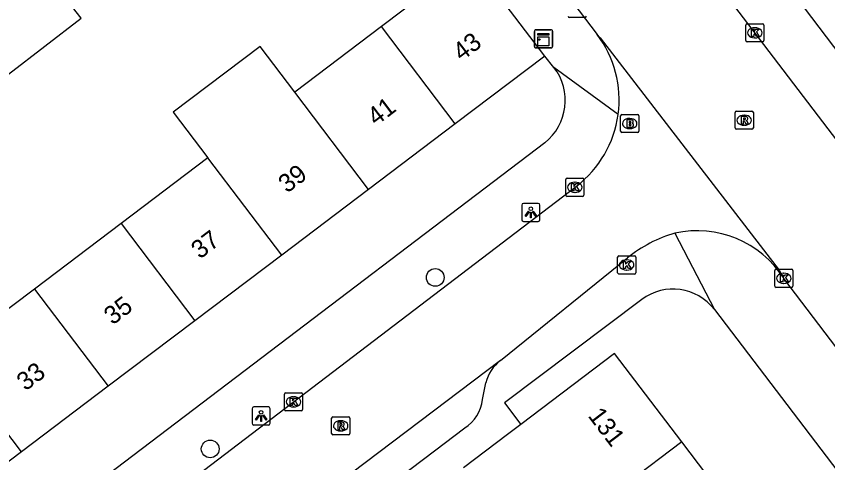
# Model space of a CAD drawing. Extents: x 160037 to 160839, y 385326 to 386441.
# Drawn here: x 160326.7 to 160371.43, y 385868.72 to 385893.36 of the extents above; entities that cross this region are included whole.
import ezdxf

# ---------------------------------------------------------------- set-up
doc = ezdxf.new("R2010")
doc.units = 0
for name, color, linetype in [('IMGEO_Boom', 7, 'Continuous'), ('IMGEO_Brandkraan', 7, 'Continuous'), ('IMGEO_Kast', 7, 'Continuous'), ('IMGEO_Kolk', 7, 'Continuous'), ('IMGEO_Lichtpunt', 7, 'Continuous'), ('IMGEO_Pand', 7, 'Continuous'), ('IMGEO_Pand_nummerreeks', 7, 'Continuous'), ('IMGEO_Rijbaan_lokaal_open', 7, 'Continuous'), ('IMGEO_Rioolput', 7, 'Continuous'), ('IMGEO_Voetpad_open', 7, 'Continuous')]:
    doc.layers.add(name, color=color, linetype=linetype)

msp = doc.modelspace()

# ---------------------------------------------------------------- linework, layer by layer
at = {"layer": 'IMGEO_Boom'}
for centre in [(160349.794, 385878.947), (160337.388, 385869.482)]:
    msp.add_circle(centre, 0.489, dxfattribs=at)
at = {"layer": 'IMGEO_Brandkraan'}
for p, q in [((160360.014, 385887.015), (160360.014, 385887.867)), ((160360.089, 385887.941), (160360.941, 385887.941)), ((160361.015, 385887.867), (160361.015, 385887.015)), ((160360.502, 385887.721), (160360.527, 385887.721)), ((160360.941, 385886.941), (160360.089, 385886.941)), ((160360.525, 385887.161), (160360.5, 385887.161))]:
    msp.add_line(p, q, dxfattribs=at)
for points in [[(160360.014, 385887.015), (160360.014, 385887.867)], [(160360.089, 385887.941), (160360.941, 385887.941)], [(160361.015, 385887.867), (160361.015, 385887.015)], [(160360.362, 385887.641), (160360.362, 385887.241), (160360.575, 385887.241)], [(160360.593, 385887.641), (160360.362, 385887.641)], [(160360.541, 385887.56), (160360.487, 385887.56), (160360.487, 385887.484)], [(160360.487, 385887.484), (160360.54, 385887.484)], [(160360.549, 385887.408), (160360.487, 385887.408), (160360.487, 385887.327)], [(160360.487, 385887.327), (160360.549, 385887.327)], [(160360.941, 385886.941), (160360.089, 385886.941)]]:
    msp.add_lwpolyline(points, dxfattribs=at)
for centre, radius, start, end in [((160360.091, 385887.865), 0.0765, 91.552, 178.448), ((160360.091, 385887.865), 0.0765, 91.552, 178.448), ((160360.939, 385887.865), 0.0765, 1.552, 88.448), ((160360.939, 385887.865), 0.0765, 1.552, 88.448), ((160360.542, 385887.522), 0.0379, 267.8285, 90.9355), ((160360.55, 385887.367), 0.0404, 269.8759, 90.5077), ((160360.597, 385887.496), 0.145, 59.4692, 91.5367), ((160360.622, 385887.543), 0.0922, 285.5137, 58.1501), ((160360.627, 385887.351), 0.105, 301.3115, 78.989), ((160360.091, 385887.017), 0.0765, 181.552, 268.448), ((160360.091, 385887.017), 0.0765, 181.552, 268.448), ((160360.581, 385887.492), 0.251, 268.6676, 293.5347), ((160360.939, 385887.017), 0.0765, 271.552, 358.448), ((160360.939, 385887.017), 0.0765, 271.552, 358.448)]:
    msp.add_arc(centre, radius, start, end, dxfattribs=at)
for centre, major_axis, ratio, start_param, end_param in [((160360.501, 385887.441), (-0.387, 0.002), 0.722429, 4.712389, 7.853982), ((160360.526, 385887.441), (-0.39, 0.002), 0.717154, 1.570796, 4.712389)]:
    msp.add_ellipse(centre, major_axis=major_axis, ratio=ratio, start_param=start_param, end_param=end_param, dxfattribs=at)
at = {"layer": 'IMGEO_Kast'}
for p, q in [((160355.259, 385891.688), (160355.259, 385892.529)), ((160355.259, 385892.529), (160355.259, 385891.688)), ((160355.334, 385892.613), (160356.175, 385892.613)), ((160356.175, 385892.613), (160355.334, 385892.613)), ((160356.259, 385892.538), (160356.259, 385891.697)), ((160356.259, 385891.697), (160356.259, 385892.538)), ((160356.184, 385891.613), (160355.343, 385891.613)), ((160355.343, 385891.613), (160356.184, 385891.613))]:
    msp.add_line(p, q, dxfattribs=at)
for points in [[(160355.454, 385892.403), (160356.054, 385892.403), (160356.054, 385892.318), (160355.454, 385892.318), (160355.454, 385892.403)], [(160355.454, 385892.228), (160356.054, 385892.228), (160356.054, 385891.739), (160355.454, 385891.739), (160355.454, 385892.228)]]:
    msp.add_lwpolyline(points, dxfattribs=at)
msp.add_circle((160355.538, 385892.077), 0.0377, dxfattribs=at)
for centre, start, end in [((160355.337, 385892.535), 92.4484, 184.2845), ((160355.337, 385892.535), 92.4484, 184.2845), ((160356.181, 385892.535), 2.4484, 94.2845), ((160356.181, 385892.535), 2.4484, 94.2845), ((160355.337, 385891.691), 182.4484, 274.2845), ((160355.337, 385891.691), 182.4484, 274.2845), ((160356.181, 385891.691), 272.4484, 4.2845), ((160356.181, 385891.691), 272.4484, 4.2845)]:
    msp.add_arc(centre, 0.0779, start, end, dxfattribs=at)
at = {"layer": 'IMGEO_Kolk'}
for p, q in [((160358.053, 385893.291), (160357.201, 385893.291)), ((160366.908, 385892.025), (160366.908, 385892.877)), ((160366.983, 385892.951), (160367.835, 385892.951)), ((160367.396, 385892.731), (160367.421, 385892.731)), ((160367.909, 385892.877), (160367.909, 385892.025)), ((160367.835, 385891.951), (160366.983, 385891.951)), ((160367.419, 385892.171), (160367.394, 385892.171)), ((160356.989, 385883.498), (160356.989, 385884.35)), ((160357.064, 385884.424), (160357.916, 385884.424)), ((160357.477, 385884.204), (160357.502, 385884.204)), ((160357.99, 385884.35), (160357.99, 385883.498)), ((160357.916, 385883.424), (160357.064, 385883.424)), ((160357.5, 385883.644), (160357.475, 385883.644)), ((160359.922, 385880.137), (160360.774, 385880.137)), ((160359.847, 385879.211), (160359.847, 385880.063)), ((160360.335, 385879.917), (160360.36, 385879.917)), ((160360.848, 385880.063), (160360.848, 385879.211)), ((160360.358, 385879.357), (160360.333, 385879.357)), ((160368.507, 385878.475), (160368.507, 385879.327)), ((160368.582, 385879.401), (160369.434, 385879.401)), ((160369.508, 385879.327), (160369.508, 385878.475)), ((160360.774, 385879.137), (160359.922, 385879.137)), ((160368.995, 385879.181), (160369.02, 385879.181)), ((160369.434, 385878.401), (160368.582, 385878.401)), ((160369.018, 385878.621), (160368.993, 385878.621)), ((160341.555, 385872.584), (160342.407, 385872.584)), ((160341.48, 385871.658), (160341.48, 385872.51)), ((160341.968, 385872.364), (160341.993, 385872.364)), ((160342.481, 385872.51), (160342.481, 385871.658)), ((160341.991, 385871.804), (160341.966, 385871.804)), ((160342.407, 385871.584), (160341.555, 385871.584))]:
    msp.add_line(p, q, dxfattribs=at)
for points in [[(160358.053, 385893.291), (160357.201, 385893.291)], [(160366.908, 385892.025), (160366.908, 385892.877)], [(160366.983, 385892.951), (160367.835, 385892.951)], [(160367.909, 385892.877), (160367.909, 385892.025)], [(160367.229, 385892.651), (160367.352, 385892.651), (160367.352, 385892.5), (160367.482, 385892.651), (160367.646, 385892.651), (160367.5, 385892.5), (160367.653, 385892.251), (160367.501, 385892.251), (160367.416, 385892.415), (160367.352, 385892.348), (160367.352, 385892.251), (160367.229, 385892.251), (160367.229, 385892.651)], [(160367.835, 385891.951), (160366.983, 385891.951)], [(160356.989, 385883.498), (160356.989, 385884.35)], [(160357.064, 385884.424), (160357.916, 385884.424)], [(160357.99, 385884.35), (160357.99, 385883.498)], [(160357.31, 385884.124), (160357.433, 385884.124), (160357.433, 385883.973), (160357.563, 385884.124), (160357.727, 385884.124), (160357.581, 385883.973), (160357.734, 385883.724), (160357.582, 385883.724), (160357.497, 385883.888), (160357.433, 385883.821), (160357.433, 385883.724), (160357.31, 385883.724), (160357.31, 385884.124)], [(160357.916, 385883.424), (160357.064, 385883.424)], [(160359.922, 385880.137), (160360.774, 385880.137)], [(160359.847, 385879.211), (160359.847, 385880.063)], [(160360.168, 385879.837), (160360.291, 385879.837), (160360.291, 385879.686), (160360.421, 385879.837), (160360.585, 385879.837), (160360.439, 385879.686), (160360.592, 385879.437), (160360.44, 385879.437), (160360.355, 385879.601), (160360.291, 385879.534), (160360.291, 385879.437), (160360.168, 385879.437), (160360.168, 385879.837)], [(160360.848, 385880.063), (160360.848, 385879.211)], [(160368.507, 385878.475), (160368.507, 385879.327)], [(160368.582, 385879.401), (160369.434, 385879.401)], [(160369.508, 385879.327), (160369.508, 385878.475)], [(160360.774, 385879.137), (160359.922, 385879.137)], [(160368.828, 385879.101), (160368.951, 385879.101), (160368.951, 385878.95), (160369.081, 385879.101), (160369.245, 385879.101), (160369.099, 385878.95), (160369.252, 385878.701), (160369.1, 385878.701), (160369.015, 385878.865), (160368.951, 385878.798), (160368.951, 385878.701), (160368.828, 385878.701), (160368.828, 385879.101)], [(160369.434, 385878.401), (160368.582, 385878.401)], [(160341.555, 385872.584), (160342.407, 385872.584)], [(160341.48, 385871.658), (160341.48, 385872.51)], [(160341.801, 385872.284), (160341.924, 385872.284), (160341.924, 385872.133), (160342.054, 385872.284), (160342.218, 385872.284), (160342.072, 385872.133), (160342.225, 385871.884), (160342.073, 385871.884), (160341.988, 385872.048), (160341.924, 385871.981), (160341.924, 385871.884), (160341.801, 385871.884), (160341.801, 385872.284)], [(160342.481, 385872.51), (160342.481, 385871.658)], [(160342.407, 385871.584), (160341.555, 385871.584)]]:
    msp.add_lwpolyline(points, dxfattribs=at)
for centre, start, end in [((160357.203, 385893.367), 181.552, 268.448), ((160357.203, 385893.367), 181.552, 268.448), ((160358.051, 385893.367), 271.552, 358.448), ((160358.051, 385893.367), 271.552, 358.448), ((160366.985, 385892.875), 91.552, 178.448), ((160366.985, 385892.875), 91.552, 178.448), ((160367.833, 385892.875), 1.552, 88.448), ((160367.833, 385892.875), 1.552, 88.448), ((160366.985, 385892.027), 181.552, 268.448), ((160366.985, 385892.027), 181.552, 268.448), ((160367.833, 385892.027), 271.552, 358.448), ((160367.833, 385892.027), 271.552, 358.448), ((160357.066, 385884.348), 91.552, 178.448), ((160357.066, 385884.348), 91.552, 178.448), ((160357.914, 385884.348), 1.552, 88.448), ((160357.914, 385884.348), 1.552, 88.448), ((160357.066, 385883.5), 181.552, 268.448), ((160357.066, 385883.5), 181.552, 268.448), ((160357.914, 385883.5), 271.552, 358.448), ((160357.914, 385883.5), 271.552, 358.448), ((160359.924, 385880.061), 91.552, 178.448), ((160359.924, 385880.061), 91.552, 178.448), ((160360.772, 385880.061), 1.552, 88.448), ((160360.772, 385880.061), 1.552, 88.448), ((160368.584, 385879.325), 91.552, 178.448), ((160368.584, 385879.325), 91.552, 178.448), ((160369.432, 385879.325), 1.552, 88.448), ((160369.432, 385879.325), 1.552, 88.448), ((160359.924, 385879.213), 181.552, 268.448), ((160359.924, 385879.213), 181.552, 268.448), ((160360.772, 385879.213), 271.552, 358.448), ((160360.772, 385879.213), 271.552, 358.448), ((160368.584, 385878.477), 181.552, 268.448), ((160368.584, 385878.477), 181.552, 268.448), ((160369.432, 385878.477), 271.552, 358.448), ((160369.432, 385878.477), 271.552, 358.448), ((160341.557, 385872.508), 91.552, 178.448), ((160341.557, 385872.508), 91.552, 178.448), ((160342.405, 385872.508), 1.552, 88.448), ((160342.405, 385872.508), 1.552, 88.448), ((160341.557, 385871.66), 181.552, 268.448), ((160341.557, 385871.66), 181.552, 268.448), ((160342.405, 385871.66), 271.552, 358.448), ((160342.405, 385871.66), 271.552, 358.448)]:
    msp.add_arc(centre, 0.0765, start, end, dxfattribs=at)
for centre, major_axis, ratio, start_param, end_param in [((160367.395, 385892.451), (-0.387, 0.002), 0.722429, 4.712389, 7.853982), ((160367.42, 385892.451), (-0.39, 0.002), 0.717154, 1.570796, 4.712389), ((160357.476, 385883.924), (-0.387, 0.002), 0.722429, 4.712389, 7.853982), ((160357.501, 385883.924), (-0.39, 0.002), 0.717154, 1.570796, 4.712389), ((160360.334, 385879.637), (-0.387, 0.002), 0.722429, 4.712389, 7.853982), ((160360.359, 385879.637), (-0.39, 0.002), 0.717154, 1.570796, 4.712389), ((160368.994, 385878.901), (-0.387, 0.002), 0.722429, 4.712389, 7.853982), ((160369.019, 385878.901), (-0.39, 0.002), 0.717154, 1.570796, 4.712389), ((160341.967, 385872.084), (-0.387, 0.002), 0.722429, 4.712389, 7.853982), ((160341.992, 385872.084), (-0.39, 0.002), 0.717154, 1.570796, 4.712389)]:
    msp.add_ellipse(centre, major_axis=major_axis, ratio=ratio, start_param=start_param, end_param=end_param, dxfattribs=at)
at = {"layer": 'IMGEO_Lichtpunt'}
for p, q in [((160354.565, 385882.941), (160354.565, 385882.134)), ((160354.565, 385882.941), (160354.565, 385882.134)), ((160355.467, 385883.036), (160354.659, 385883.036)), ((160355.467, 385883.036), (160354.659, 385883.036)), ((160355.561, 385882.134), (160355.561, 385882.941)), ((160355.561, 385882.134), (160355.561, 385882.941)), ((160354.659, 385882.04), (160355.467, 385882.04)), ((160354.659, 385882.04), (160355.467, 385882.04)), ((160339.698, 385871.706), (160339.698, 385870.899)), ((160339.698, 385871.706), (160339.698, 385870.899)), ((160340.6, 385871.801), (160339.792, 385871.801)), ((160340.6, 385871.801), (160339.792, 385871.801)), ((160340.694, 385870.899), (160340.694, 385871.706)), ((160340.694, 385870.899), (160340.694, 385871.706)), ((160339.792, 385870.805), (160340.6, 385870.805)), ((160339.792, 385870.805), (160340.6, 385870.805))]:
    msp.add_line(p, q, dxfattribs=at)
for points in [[(160354.939, 385882.605), (160354.978, 385882.577), (160354.79, 385882.315), (160354.752, 385882.342), (160354.939, 385882.605)], [(160355.041, 385882.557), (160355.088, 385882.557), (160355.088, 385882.235), (160355.041, 385882.235), (160355.041, 385882.557)], [(160355.151, 385882.577), (160355.189, 385882.604), (160355.376, 385882.342), (160355.337, 385882.314), (160355.151, 385882.577)], [(160340.072, 385871.37), (160340.111, 385871.342), (160339.923, 385871.08), (160339.885, 385871.107), (160340.072, 385871.37)], [(160340.174, 385871.322), (160340.221, 385871.322), (160340.221, 385871), (160340.174, 385871), (160340.174, 385871.322)], [(160340.284, 385871.342), (160340.322, 385871.369), (160340.509, 385871.107), (160340.47, 385871.079), (160340.284, 385871.342)]]:
    msp.add_lwpolyline(points, dxfattribs=at)
for centre in [(160355.064, 385882.739), (160340.197, 385871.504)]:
    msp.add_circle(centre, 0.0994, dxfattribs=at)
for centre, start, end in [((160354.659, 385882.941), 90, 180), ((160354.659, 385882.941), 90, 180), ((160355.467, 385882.941), 0, 90), ((160355.467, 385882.941), 0, 90), ((160354.659, 385882.134), 180, 270), ((160354.659, 385882.134), 180, 270), ((160355.467, 385882.134), 270, 0), ((160355.467, 385882.134), 270, 360), ((160339.792, 385871.706), 90, 180), ((160339.792, 385871.706), 90, 180), ((160340.6, 385871.706), 0, 90), ((160340.6, 385871.706), 0, 90), ((160339.792, 385870.899), 180, 270), ((160339.792, 385870.899), 180, 270), ((160340.6, 385870.899), 270, 0), ((160340.6, 385870.899), 270, 360)]:
    msp.add_arc(centre, 0.0946, start, end, dxfattribs=at)
at = {"layer": 'IMGEO_Pand'}
for points in [[(160351.765, 385896.532), (160346.831, 385892.796)], [(160355.831, 385891.162), (160351.765, 385896.532)], [(160326.279, 385890.159), (160330.268, 385893.263), (160328.841, 385895.097)], [(160346.831, 385892.796), (160342.048, 385889.175)], [(160350.897, 385887.426), (160346.831, 385892.796)], [(160342.048, 385889.175), (160340.138, 385891.697), (160335.354, 385888.075), (160337.264, 385885.553)], [(160355.831, 385891.162), (160350.897, 385887.426)], [(160346.114, 385883.805), (160342.048, 385889.175)], [(160350.897, 385887.426), (160346.114, 385883.805)], [(160337.264, 385885.553), (160332.481, 385881.931)], [(160341.33, 385880.183), (160337.264, 385885.553)], [(160346.114, 385883.805), (160341.33, 385880.183)], [(160332.481, 385881.931), (160327.697, 385878.309)], [(160332.481, 385881.931), (160336.547, 385876.561)], [(160341.33, 385880.183), (160336.547, 385876.561)], [(160327.697, 385878.309), (160322.914, 385874.688)], [(160327.697, 385878.309), (160331.763, 385872.939)], [(160336.547, 385876.561), (160331.763, 385872.939)], [(160326.98, 385869.318), (160322.914, 385874.688)], [(160363.386, 385869.872), (160359.681, 385874.747), (160354.522, 385870.841)], [(160331.763, 385872.939), (160326.98, 385869.318)], [(160354.522, 385870.841), (160353.782, 385870.28), (160351.36, 385868.446)], [(160363.386, 385869.872), (160357.473, 385865.379)], [(160367.015, 385865.095), (160363.386, 385869.872)], [(160326.98, 385869.318), (160322.196, 385865.696)]]:
    msp.add_lwpolyline(points, dxfattribs=at)
at = {"layer": 'IMGEO_Rijbaan_lokaal_open'}
for points in [[(160332.303, 385927.233), (160345.107, 385910.299), (160358.716, 385892.358)], [(160354.228, 385909.797), (160362.982, 385898.266), (160380.955, 385874.652), (160383.666, 385871.067)], [(160358.716, 385892.358), (160358.891, 385892.166), (160368.75, 385879.341), (160369.011, 385878.899)], [(160310.316, 385848.008), (160334.468, 385866.348), (160357.581, 385883.992)], [(160353.387, 385874.369), (160360.393, 385880.034)], [(160427.481, 385801.96), (160410.888, 385823.854), (160400.824, 385837.058), (160390.932, 385850.046), (160369.011, 385878.899)], [(160353.387, 385874.369), (160336.283, 385861.419), (160326.328, 385853.868)]]:
    msp.add_lwpolyline(points, dxfattribs=at)
for centre, radius, start, end in [((160353.951, 385888.744), 5.98, 352.2714, 37.1761), ((160353.955, 385888.742), 5.976, 307.3552, 352.2836), ((160364.227, 385875.857), 5.67, 32.4528, 102.4024), ((160365.116, 385874.144), 7.55, 106.2089, 128.729)]:
    msp.add_arc(centre, radius, start, end, dxfattribs=at)
at = {"layer": 'IMGEO_Rioolput'}
for p, q in [((160366.329, 385887.198), (160366.329, 385888.05)), ((160366.404, 385888.124), (160367.256, 385888.124)), ((160366.817, 385887.904), (160366.842, 385887.904)), ((160367.33, 385888.05), (160367.33, 385887.198)), ((160366.84, 385887.344), (160366.815, 385887.344)), ((160367.256, 385887.124), (160366.404, 385887.124)), ((160344.158, 385871.26), (160345.01, 385871.26)), ((160344.083, 385870.334), (160344.083, 385871.186)), ((160344.571, 385871.04), (160344.596, 385871.04)), ((160345.084, 385871.186), (160345.084, 385870.334)), ((160344.594, 385870.48), (160344.569, 385870.48)), ((160345.01, 385870.26), (160344.158, 385870.26))]:
    msp.add_line(p, q, dxfattribs=at)
for points in [[(160366.329, 385887.198), (160366.329, 385888.05)], [(160366.404, 385888.124), (160367.256, 385888.124)], [(160366.918, 385887.822), (160366.666, 385887.824), (160366.666, 385887.424)], [(160366.844, 385887.743), (160366.79, 385887.743), (160366.79, 385887.662)], [(160367.33, 385888.05), (160367.33, 385887.198)], [(160366.666, 385887.424), (160366.79, 385887.424), (160366.79, 385887.586), (160366.801, 385887.586)], [(160366.79, 385887.662), (160366.842, 385887.662)], [(160366.848, 385887.557), (160366.919, 385887.424), (160367.059, 385887.424), (160366.994, 385887.55)], [(160367.256, 385887.124), (160366.404, 385887.124)], [(160344.158, 385871.26), (160345.01, 385871.26)], [(160344.083, 385870.334), (160344.083, 385871.186)], [(160344.672, 385870.958), (160344.42, 385870.96), (160344.42, 385870.56)], [(160344.598, 385870.879), (160344.544, 385870.879), (160344.544, 385870.798)], [(160344.544, 385870.798), (160344.596, 385870.798)], [(160345.084, 385871.186), (160345.084, 385870.334)], [(160344.42, 385870.56), (160344.544, 385870.56), (160344.544, 385870.722), (160344.555, 385870.722)], [(160344.602, 385870.693), (160344.673, 385870.56), (160344.813, 385870.56), (160344.748, 385870.686)], [(160345.01, 385870.26), (160344.158, 385870.26)]]:
    msp.add_lwpolyline(points, dxfattribs=at)
for centre, radius, start, end in [((160366.406, 385888.048), 0.0765, 91.552, 178.448), ((160366.406, 385888.048), 0.0765, 91.552, 178.448), ((160366.85, 385887.647), 0.0964, 77.0061, 93.1865), ((160366.917, 385887.712), 0.109, 350.3612, 89.416), ((160367.254, 385888.048), 0.0765, 1.552, 88.448), ((160367.254, 385888.048), 0.0765, 1.552, 88.448), ((160366.8, 385887.533), 0.0533, 26.0293, 88.6989), ((160366.826, 385887.851), 0.19, 274.7715, 282.9687), ((160366.864, 385887.704), 0.0378, 276.6634, 79.6772), ((160366.915, 385887.712), 0.112, 277.5842, 350.9817), ((160366.899, 385887.497), 0.108, 29.5134, 73.7905), ((160366.406, 385887.2), 0.0765, 181.552, 268.448), ((160366.406, 385887.2), 0.0765, 181.552, 268.448), ((160367.254, 385887.2), 0.0765, 271.552, 358.448), ((160367.254, 385887.2), 0.0765, 271.552, 358.448), ((160344.16, 385871.184), 0.0765, 91.552, 178.448), ((160344.16, 385871.184), 0.0765, 91.552, 178.448), ((160345.008, 385871.184), 0.0765, 1.552, 88.448), ((160345.008, 385871.184), 0.0765, 1.552, 88.448), ((160344.58, 385870.987), 0.19, 274.7715, 282.9687), ((160344.604, 385870.783), 0.0964, 77.0061, 93.1865), ((160344.618, 385870.84), 0.0378, 276.6634, 79.6772), ((160344.671, 385870.848), 0.109, 350.3612, 89.416), ((160344.669, 385870.848), 0.112, 277.5842, 350.9817), ((160344.16, 385870.336), 0.0765, 181.552, 268.448), ((160344.16, 385870.336), 0.0765, 181.552, 268.448), ((160344.554, 385870.669), 0.0533, 26.0293, 88.6989), ((160344.653, 385870.633), 0.108, 29.5134, 73.7905), ((160345.008, 385870.336), 0.0765, 271.552, 358.448), ((160345.008, 385870.336), 0.0765, 271.552, 358.448)]:
    msp.add_arc(centre, radius, start, end, dxfattribs=at)
for centre, major_axis, ratio, start_param, end_param in [((160366.816, 385887.624), (-0.387, 0.002), 0.722429, 4.712389, 7.853982), ((160366.841, 385887.624), (-0.39, 0.002), 0.717154, 1.570796, 4.712389), ((160344.57, 385870.76), (-0.387, 0.002), 0.722429, 4.712389, 7.853982), ((160344.595, 385870.76), (-0.39, 0.002), 0.717154, 1.570796, 4.712389)]:
    msp.add_ellipse(centre, major_axis=major_axis, ratio=ratio, start_param=start_param, end_param=end_param, dxfattribs=at)
at = {"layer": 'IMGEO_Voetpad_open'}
for points in [[(160365.521, 385899.939), (160385.064, 385874.105), (160385.912, 385874.747)], [(160356.339, 385890.539), (160355.831, 385891.162)], [(160359.877, 385887.94), (160356.339, 385890.539)], [(160355.835, 385886.372), (160300.518, 385844.329)], [(160363.009, 385881.394), (160365.182, 385877.181)], [(160361.189, 385877.731), (160353.622, 385872.023), (160354.522, 385870.841)], [(160365.182, 385877.181), (160425.684, 385797.636)], [(160352.408, 385872.206), (160352.578, 385873.139)], [(160329.781, 385854.21), (160336.673, 385859.456), (160349.751, 385869.377), (160351.421, 385870.644)]]:
    msp.add_lwpolyline(points, dxfattribs=at)
for centre, radius, start, end in [((160353.962, 385888.713), 2.998, 308.6711, 37.536), ((160362.909, 385875.449), 2.857, 37.3033, 127.0114), ((160354.865, 385872.516), 2.371, 128.5764, 164.7559), ((160350.273, 385872.462), 2.15, 302.2652, 353.1587)]:
    msp.add_arc(centre, radius, start, end, dxfattribs=at)

# ---------------------------------------------------------------- texts
at = {"layer": 'IMGEO_Pand_nummerreeks'}
for s, rotation, p in [('43', 37.1311, (160351.246, 385890.852)), ('41', 37.1311, (160346.529, 385887.28)), ('39', 37.1334, (160341.629, 385883.569)), ('37', 37.1311, (160336.821, 385879.929)), ('35', 37.1311, (160332.012, 385876.289)), ('33', 37.1311, (160327.204, 385872.648)), ('131', 307.2297, (160358.179, 385871.303))]:
    msp.add_text(s, height=1, rotation=rotation, dxfattribs=at).set_placement(p)

doc.saveas('drawing.dxf')
